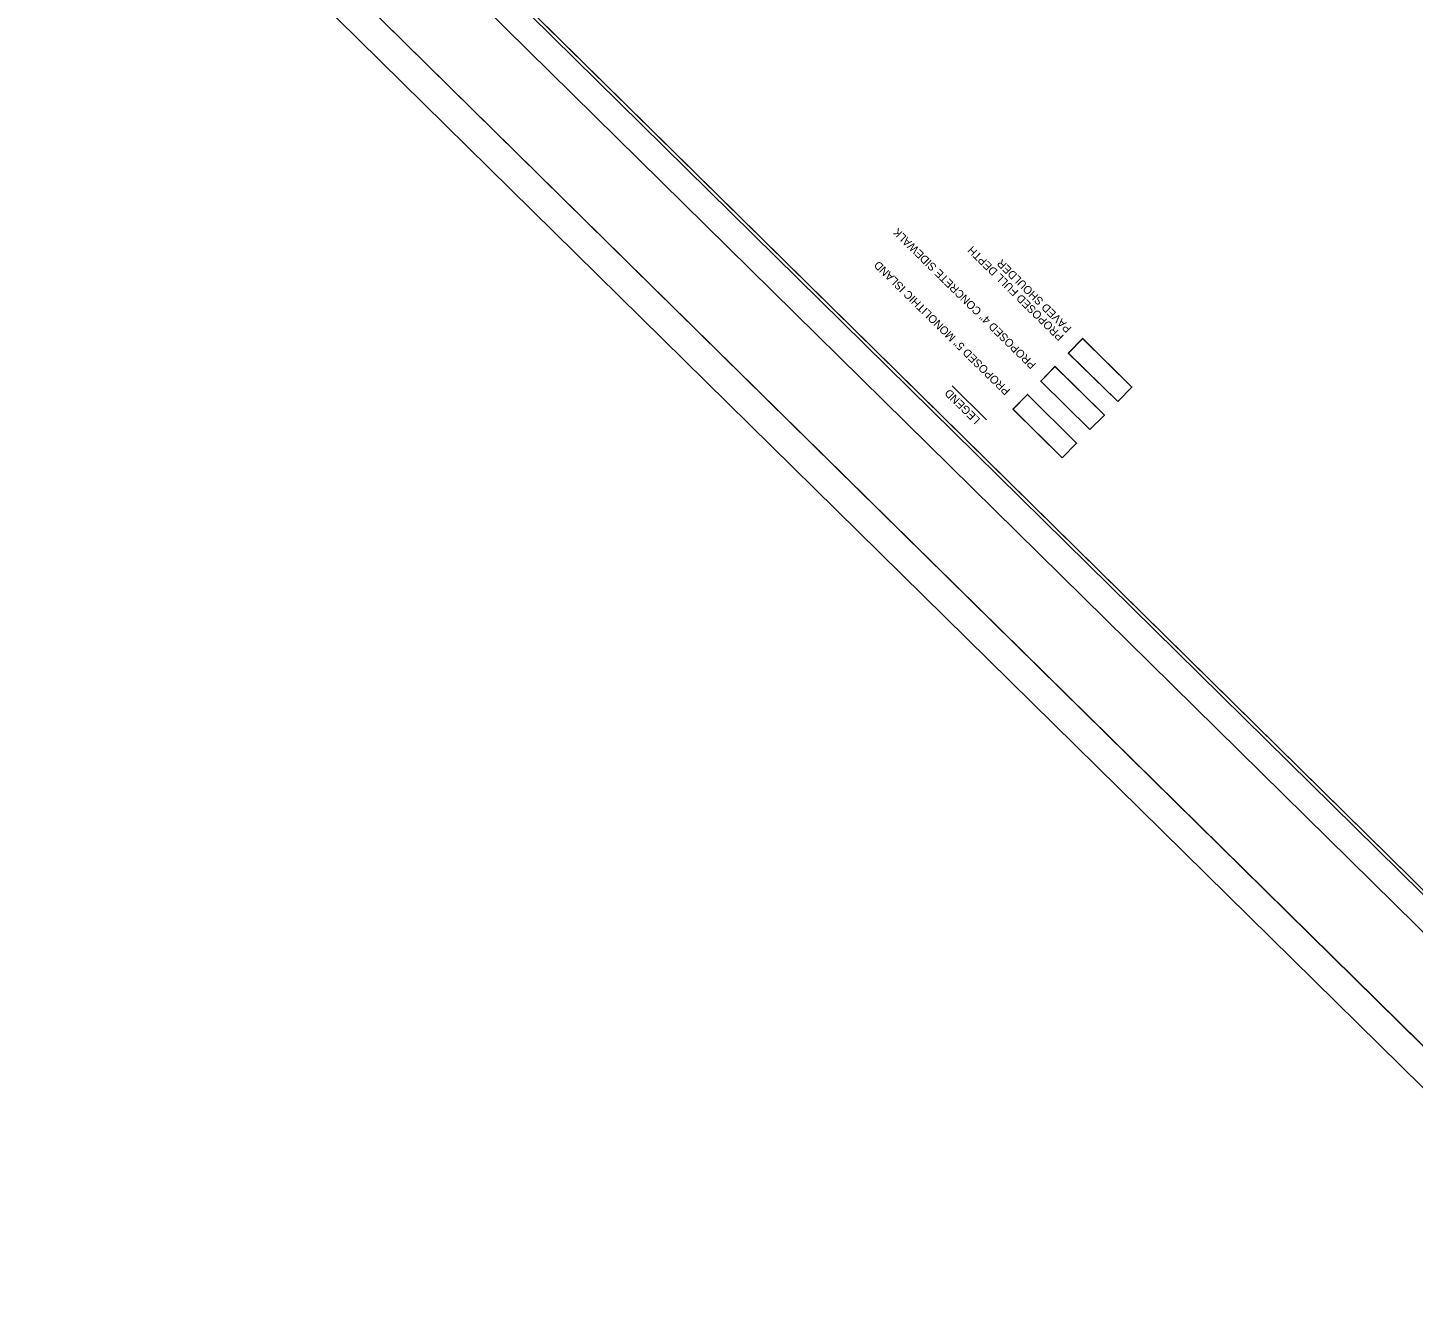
# Model space of a CAD drawing. Extents: x 1266642 to 1268668, y 770349 to 772370.
# Drawn here: x 1266642 to 1267681, y 770349 to 771295 of the extents above; entities that cross this region are included whole.
import ezdxf

# ---------------------------------------------------------------- set-up
doc = ezdxf.new("R2010")
doc.units = 0
for name, color, linetype in [('Exist DTM Crownline', 7, 'Continuous'), ('Exist Roads EOT', 7, 'Continuous'), ('Exist Utilities Power Pole CELL', 7, 'Continuous'), ('Exist Utilities Power Pole Cogo Elevation', 7, 'Continuous'), ('Prop Conc 1ft 6in Curb and Gutter', 7, 'Continuous'), ('Prop Conc 4in Sidewalk', 7, 'Continuous'), ('Prop EOT', 7, 'Continuous'), ('Prop Horizontal Alignment Direction Label', 7, 'Continuous'), ('Prop Horizontal Alignment Station Label', 7, 'Continuous'), ('Prop Plan Preparation Crest', 7, 'Continuous'), ('Prop Plan Preparation Watershed Post Construction', 7, 'Continuous'), ('Typical Terminator CELL', 7, 'Continuous')]:
    doc.layers.add(name, color=color, linetype=linetype)

msp = doc.modelspace()

# ---------------------------------------------------------------- linework, layer by layer
at = {"layer": 'Exist DTM Crownline'}
msp.add_lwpolyline([(1267459.1, 771014.4), (1267469.8, 771025.3), (1267432.9, 771061.6), (1267422.2, 771050.8)], close=True, dxfattribs=at)
at = {"layer": 'Exist Utilities Power Pole CELL'}
msp.add_lwpolyline([(1267796.9, 770541.1), (1268533.9, 771289), (1267501, 772306.7), (1266885.9, 771682.4), (1266992.8, 771577.1), (1266870.9, 771453.5)], close=True, dxfattribs=at)
at = {"layer": 'Exist Utilities Power Pole Cogo Elevation'}
msp.add_lwpolyline([(1267417.6, 770972.3), (1267428.3, 770983.2), (1267391.5, 771019.6), (1267380.7, 771008.7)], close=True, dxfattribs=at)
at = {"layer": 'Prop Conc 1ft 6in Curb and Gutter'}
msp.add_line((1267360.8, 771000.8), (1267335, 771026.3), dxfattribs=at)
for points in [[(1266728.4, 771593.9), (1267796.9, 770541.1), (1268533.9, 771289), (1267465.4, 772341.8)], [(1267459.1, 771014.4), (1267469.8, 771025.3), (1267432.8, 771061.7), (1267422.1, 771050.8)], [(1267438.3, 770993.4), (1267449.1, 771004.3), (1267412.1, 771040.7), (1267401.4, 771029.8)], [(1267417.6, 770972.3), (1267428.3, 770983.2), (1267391.4, 771019.7), (1267380.6, 771008.8)]]:
    msp.add_lwpolyline(points, close=True, dxfattribs=at)
at = {"layer": 'Prop Conc 4in Sidewalk'}
msp.add_line((1266642, 771530.4), (1267841.2, 770348.8), dxfattribs=at)
at = {"layer": 'Prop EOT'}
msp.add_lwpolyline([(1268645, 771183.1), (1267458.3, 772352.4), (1266717.8, 771600.9), (1267904.5, 770431.6)], close=True, dxfattribs=at)
at = {"layer": 'Prop Horizontal Alignment Direction Label'}
msp.add_lwpolyline([(1267438.3, 770993.4), (1267449.1, 771004.3), (1267412.2, 771040.6), (1267401.5, 771029.7)], close=True, dxfattribs=at)
at = {"layer": 'Prop Horizontal Alignment Station Label'}
msp.add_lwpolyline([(1268668.3, 771188.2), (1267469.1, 772369.8), (1266700.6, 771589.8), (1267899.8, 770408.2)], close=True, dxfattribs=at)
at = {"layer": 'Prop Plan Preparation Crest'}
msp.add_lwpolyline([(1267738.4, 770481.7), (1268475.4, 771229.6), (1267406.9, 772282.4), (1266818.4, 771685.1), (1266988.8, 771517.2), (1266840.4, 771366.5)], close=True, dxfattribs=at)
at = {"layer": 'Prop Plan Preparation Watershed Post Construction'}
msp.add_lwpolyline([(1268439.7, 771264.7), (1267442.5, 772247.3), (1266854, 771650), (1266988.8, 771517.2), (1266840.4, 771366.5), (1267702.8, 770516.8)], close=True, dxfattribs=at)
at = {"layer": 'Typical Terminator CELL'}
msp.add_lwpolyline([(1268439.7, 771264.7), (1267442.5, 772247.3), (1266854, 771650), (1266988.8, 771517.2), (1266840.4, 771366.5), (1267702.8, 770516.8)], close=True, dxfattribs=at)

# ---------------------------------------------------------------- texts
at = {"layer": 'Exist Roads EOT'}
for s, p in [('PROPOSED 4" CONCRETE SIDEWALK', (1267398.3, 771042.5)), ('PROPOSED FULL DEPTH', (1267419.1, 771063.6)), ('PROPOSED 5" MONOLITHIC ISLAND', (1267378.9, 771022.9)), ('PAVED SHOULDER', (1267424.9, 771069.6)), ('LEGEND', (1267356.5, 771001.2))]:
    msp.add_text(s, height=6, rotation=135.4239, dxfattribs=at).set_placement(p)

doc.saveas('drawing.dxf')
